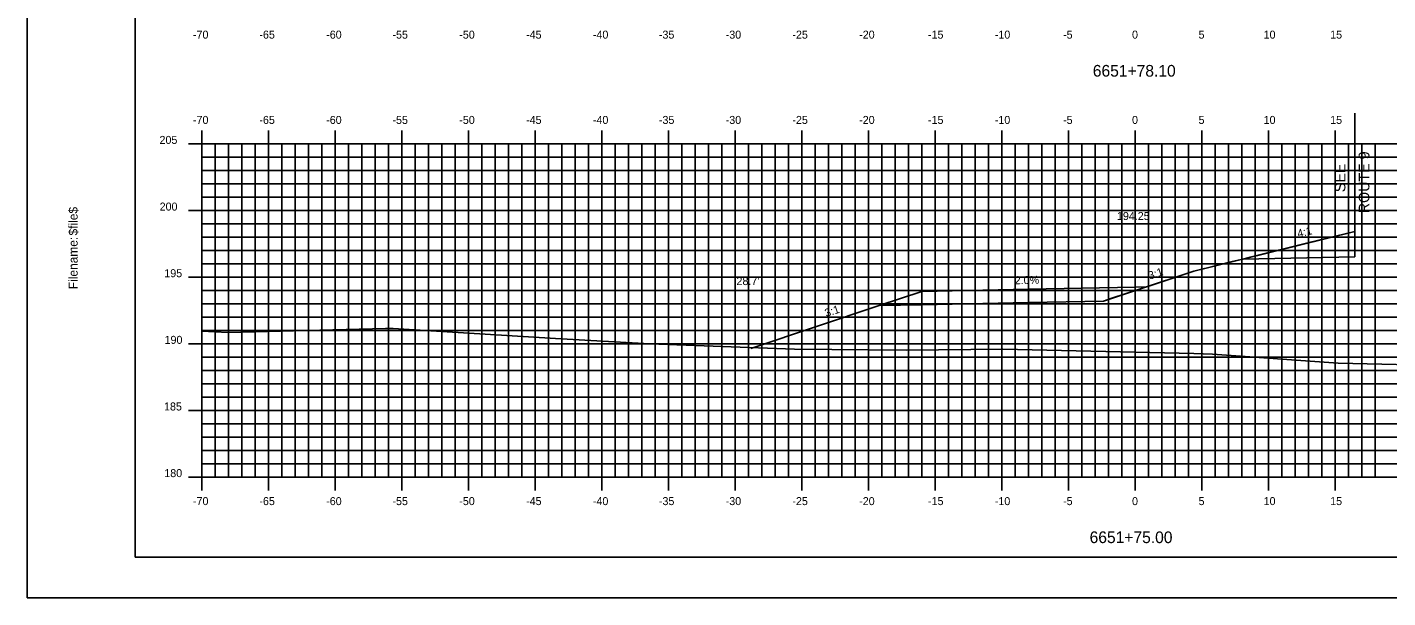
# Model space of a CAD drawing. Extents: x 1723764 to 1723936, y 458501 to 458611.
# Drawn here: x 1723764.4 to 1723866.5, y 458501.2 to 458544 of the extents above; entities that cross this region are included whole.
import ezdxf

# ---------------------------------------------------------------- set-up
doc = ezdxf.new("R2010")
doc.units = 0
for name, color, linetype in [('ANNOTATION', 7, 'Continuous'), ('BORDER', 7, 'Continuous'), ('D_Roadway_Centerline', 7, 'Continuous'), ('D_Roadway_Centerline_Text', 7, 'Continuous'), ('D_Roadway_Drive_Gravel', 7, 'Continuous'), ('D_Roadway_Edge_Shoulder', 7, 'Continuous'), ('D_Roadway_SlopeLines', 7, 'Continuous'), ('D_Roadway_SubGrade', 7, 'Continuous'), ('D_Text_Standard', 7, 'Continuous'), ('H_V ANNOTATION', 7, 'Continuous'), ('MAJOR', 7, 'Continuous'), ('MINOR', 7, 'Continuous'), ('PLOT BOUNDARY', 7, 'Continuous'), ('S_Roadway_Centerline', 7, 'Continuous')]:
    doc.layers.add(name, color=color, linetype=linetype)

msp = doc.modelspace()

# ---------------------------------------------------------------- linework, layer by layer
msp.add_lwpolyline([(1723818.71, 458519.91), (1723818.72, 458519.91), (1723818.79, 458519.93), (1723818.8, 458519.94), (1723818.87, 458519.96), (1723828.35, 458523.12), (1723831.54, 458524.18), (1723839.54, 458524.34), (1723847.54, 458524.5), (1723848.36, 458524.52)])
at = {"layer": 'BORDER'}
msp.add_lwpolyline([(1723772.54, 458504.25), (1723932.54, 458504.25), (1723932.54, 458609.25), (1723772.54, 458609.25)], close=True, dxfattribs=at)
at = {"layer": 'D_Roadway_Centerline'}
msp.add_lwpolyline([(1723845.15, 458523.46), (1723845.79, 458523.67), (1723847.86, 458524.35), (1723851.94, 458525.7), (1723852.77, 458525.91), (1723854.82, 458526.42), (1723855.03, 458526.47), (1723855.6, 458526.61), (1723856.08, 458526.73), (1723856.16, 458526.75), (1723860.49, 458527.83), (1723864, 458528.69)], dxfattribs=at)
at = {"layer": 'D_Roadway_Drive_Gravel'}
msp.add_lwpolyline([(1723847.54, 458524.5), (1723839.54, 458524.34), (1723831.54, 458524.18), (1723828.35, 458523.12), (1723831.54, 458523.18), (1723839.54, 458523.34), (1723845.15, 458523.46)], dxfattribs=at)
at = {"layer": 'D_Roadway_Edge_Shoulder'}
msp.add_line((1723864, 458528.69), (1723864, 458528.44), dxfattribs=at)
msp.add_line((1723864, 458528.69), (1723864, 458528.44), dxfattribs=at)
at = {"layer": 'D_Roadway_SlopeLines'}
for points in [[(1723864, 458528.69), (1723851.94, 458525.7), (1723845.15, 458523.46)], [(1723864, 458528.69), (1723851.94, 458525.7), (1723845.15, 458523.46)], [(1723864, 458528.69), (1723851.94, 458525.7), (1723845.15, 458523.46)], [(1723864, 458528.69), (1723851.94, 458525.7), (1723845.15, 458523.46)], [(1723864, 458528.69), (1723851.94, 458525.7), (1723845.15, 458523.46)], [(1723864, 458528.69), (1723851.94, 458525.7), (1723845.15, 458523.46)], [(1723864, 458528.69), (1723851.94, 458525.7)], [(1723864, 458528.69), (1723851.94, 458525.7)], [(1723864, 458528.69), (1723855.6, 458526.61)], [(1723831.54, 458524.18), (1723828.35, 458523.12), (1723818.87, 458519.96)], [(1723847.54, 458524.5), (1723848.36, 458524.52)]]:
    msp.add_lwpolyline(points, dxfattribs=at)
at = {"layer": 'D_Roadway_SubGrade'}
msp.add_line((1723864, 458537.55), (1723864, 458526.77), dxfattribs=at)
for points in [[(1723864, 458526.77), (1723855.6, 458526.61), (1723864, 458528.69), (1723864, 458528.44)], [(1723864, 458528.44), (1723864, 458528.69), (1723855.6, 458526.61), (1723864, 458526.77)], [(1723864, 458526.77), (1723855.6, 458526.61), (1723864, 458528.69), (1723864, 458528.44)], [(1723864, 458526.77), (1723855.6, 458526.61), (1723864, 458528.69), (1723864, 458528.44)]]:
    msp.add_lwpolyline(points, dxfattribs=at)
at = {"layer": 'MAJOR'}
for p, q in [((1723777.54, 458536.26), (1723777.54, 458535.25)), ((1723782.54, 458536.26), (1723782.54, 458535.25)), ((1723787.54, 458536.26), (1723787.54, 458535.25)), ((1723792.54, 458536.26), (1723792.54, 458535.25)), ((1723797.54, 458536.26), (1723797.54, 458535.25)), ((1723802.54, 458536.26), (1723802.54, 458535.25)), ((1723807.54, 458536.26), (1723807.54, 458535.25)), ((1723812.54, 458536.26), (1723812.54, 458535.25)), ((1723817.54, 458536.26), (1723817.54, 458535.25)), ((1723822.54, 458536.26), (1723822.54, 458535.25)), ((1723827.54, 458536.26), (1723827.54, 458535.25)), ((1723832.54, 458536.26), (1723832.54, 458535.25)), ((1723837.54, 458536.26), (1723837.54, 458535.25)), ((1723842.54, 458536.26), (1723842.54, 458535.25)), ((1723847.54, 458536.26), (1723847.54, 458535.25)), ((1723852.54, 458536.26), (1723852.54, 458535.25)), ((1723857.54, 458536.26), (1723857.54, 458535.25)), ((1723862.54, 458536.26), (1723862.54, 458535.25)), ((1723776.54, 458535.25), (1723777.54, 458535.25)), ((1723777.54, 458535.25), (1723917.54, 458535.25)), ((1723777.54, 458510.25), (1723777.54, 458535.25)), ((1723777.54, 458510.25), (1723777.54, 458535.25)), ((1723777.54, 458535.25), (1723917.54, 458535.25)), ((1723782.54, 458510.25), (1723782.54, 458535.25)), ((1723787.54, 458510.25), (1723787.54, 458535.25)), ((1723792.54, 458510.25), (1723792.54, 458535.25)), ((1723797.54, 458510.25), (1723797.54, 458535.25)), ((1723802.54, 458510.25), (1723802.54, 458535.25)), ((1723807.54, 458510.25), (1723807.54, 458535.25)), ((1723812.54, 458510.25), (1723812.54, 458535.25)), ((1723817.54, 458510.25), (1723817.54, 458535.25)), ((1723822.54, 458510.25), (1723822.54, 458535.25)), ((1723827.54, 458510.25), (1723827.54, 458535.25)), ((1723832.54, 458510.25), (1723832.54, 458535.25)), ((1723837.54, 458510.25), (1723837.54, 458535.25)), ((1723842.54, 458510.25), (1723842.54, 458535.25)), ((1723847.54, 458510.25), (1723847.54, 458535.25)), ((1723852.54, 458510.25), (1723852.54, 458535.25)), ((1723857.54, 458510.25), (1723857.54, 458535.25)), ((1723862.54, 458510.25), (1723862.54, 458535.25)), ((1723776.54, 458530.25), (1723777.54, 458530.25)), ((1723777.54, 458530.25), (1723917.54, 458530.25)), ((1723776.54, 458525.25), (1723777.54, 458525.25)), ((1723777.54, 458525.25), (1723917.54, 458525.25)), ((1723776.54, 458520.25), (1723777.54, 458520.25)), ((1723777.54, 458520.25), (1723917.54, 458520.25)), ((1723776.54, 458515.25), (1723777.54, 458515.25)), ((1723777.54, 458515.25), (1723917.54, 458515.25)), ((1723776.54, 458510.25), (1723777.54, 458510.25)), ((1723777.54, 458510.25), (1723917.54, 458510.25)), ((1723777.54, 458510.25), (1723917.54, 458510.25)), ((1723777.54, 458509.25), (1723777.54, 458510.25)), ((1723782.54, 458509.25), (1723782.54, 458510.25)), ((1723787.54, 458509.25), (1723787.54, 458510.25)), ((1723792.54, 458509.25), (1723792.54, 458510.25)), ((1723797.54, 458509.25), (1723797.54, 458510.25)), ((1723802.54, 458509.25), (1723802.54, 458510.25)), ((1723807.54, 458509.25), (1723807.54, 458510.25)), ((1723812.54, 458509.25), (1723812.54, 458510.25)), ((1723817.54, 458509.25), (1723817.54, 458510.25)), ((1723822.54, 458509.25), (1723822.54, 458510.25)), ((1723827.54, 458509.25), (1723827.54, 458510.25)), ((1723832.54, 458509.25), (1723832.54, 458510.25)), ((1723837.54, 458509.25), (1723837.54, 458510.25)), ((1723842.54, 458509.25), (1723842.54, 458510.25)), ((1723847.54, 458509.25), (1723847.54, 458510.25)), ((1723852.54, 458509.25), (1723852.54, 458510.25)), ((1723857.54, 458509.25), (1723857.54, 458510.25)), ((1723862.54, 458509.25), (1723862.54, 458510.25))]:
    msp.add_line(p, q, dxfattribs=at)
at = {"layer": 'MINOR'}
for p, q in [((1723778.54, 458510.25), (1723778.54, 458535.25)), ((1723779.54, 458510.25), (1723779.54, 458535.25)), ((1723780.54, 458510.25), (1723780.54, 458535.25)), ((1723781.54, 458510.25), (1723781.54, 458535.25)), ((1723783.54, 458510.25), (1723783.54, 458535.25)), ((1723784.54, 458510.25), (1723784.54, 458535.25)), ((1723785.54, 458510.25), (1723785.54, 458535.25)), ((1723786.54, 458510.25), (1723786.54, 458535.25)), ((1723788.54, 458510.25), (1723788.54, 458535.25)), ((1723789.54, 458510.25), (1723789.54, 458535.25)), ((1723790.54, 458510.25), (1723790.54, 458535.25)), ((1723791.54, 458510.25), (1723791.54, 458535.25)), ((1723793.54, 458510.25), (1723793.54, 458535.25)), ((1723794.54, 458510.25), (1723794.54, 458535.25)), ((1723795.54, 458510.25), (1723795.54, 458535.25)), ((1723796.54, 458510.25), (1723796.54, 458535.25)), ((1723798.54, 458510.25), (1723798.54, 458535.25)), ((1723799.54, 458510.25), (1723799.54, 458535.25)), ((1723800.54, 458510.25), (1723800.54, 458535.25)), ((1723801.54, 458510.25), (1723801.54, 458535.25)), ((1723803.54, 458510.25), (1723803.54, 458535.25)), ((1723804.54, 458510.25), (1723804.54, 458535.25)), ((1723805.54, 458510.25), (1723805.54, 458535.25)), ((1723806.54, 458510.25), (1723806.54, 458535.25)), ((1723808.54, 458510.25), (1723808.54, 458535.25)), ((1723809.54, 458510.25), (1723809.54, 458535.25)), ((1723810.54, 458510.25), (1723810.54, 458535.25)), ((1723811.54, 458510.25), (1723811.54, 458535.25)), ((1723813.54, 458510.25), (1723813.54, 458535.25)), ((1723814.54, 458510.25), (1723814.54, 458535.25)), ((1723815.54, 458510.25), (1723815.54, 458535.25)), ((1723816.54, 458510.25), (1723816.54, 458535.25)), ((1723818.54, 458510.25), (1723818.54, 458535.25)), ((1723819.54, 458510.25), (1723819.54, 458535.25)), ((1723820.54, 458510.25), (1723820.54, 458535.25)), ((1723821.54, 458510.25), (1723821.54, 458535.25)), ((1723823.54, 458510.25), (1723823.54, 458535.25)), ((1723824.54, 458510.25), (1723824.54, 458535.25)), ((1723825.54, 458510.25), (1723825.54, 458535.25)), ((1723826.54, 458510.25), (1723826.54, 458535.25)), ((1723828.54, 458510.25), (1723828.54, 458535.25)), ((1723829.54, 458510.25), (1723829.54, 458535.25)), ((1723830.54, 458510.25), (1723830.54, 458535.25)), ((1723831.54, 458510.25), (1723831.54, 458535.25)), ((1723833.54, 458510.25), (1723833.54, 458535.25)), ((1723834.54, 458510.25), (1723834.54, 458535.25)), ((1723835.54, 458510.25), (1723835.54, 458535.25)), ((1723836.54, 458510.25), (1723836.54, 458535.25)), ((1723838.54, 458510.25), (1723838.54, 458535.25)), ((1723839.54, 458510.25), (1723839.54, 458535.25)), ((1723840.54, 458510.25), (1723840.54, 458535.25)), ((1723841.54, 458510.25), (1723841.54, 458535.25)), ((1723843.54, 458510.25), (1723843.54, 458535.25)), ((1723844.54, 458510.25), (1723844.54, 458535.25)), ((1723845.54, 458510.25), (1723845.54, 458535.25)), ((1723846.54, 458510.25), (1723846.54, 458535.25)), ((1723848.54, 458510.25), (1723848.54, 458535.25)), ((1723849.54, 458510.25), (1723849.54, 458535.25)), ((1723850.54, 458510.25), (1723850.54, 458535.25)), ((1723851.54, 458510.25), (1723851.54, 458535.25)), ((1723853.54, 458510.25), (1723853.54, 458535.25)), ((1723854.54, 458510.25), (1723854.54, 458535.25)), ((1723855.54, 458510.25), (1723855.54, 458535.25)), ((1723856.54, 458510.25), (1723856.54, 458535.25)), ((1723858.54, 458510.25), (1723858.54, 458535.25)), ((1723859.54, 458510.25), (1723859.54, 458535.25)), ((1723860.54, 458510.25), (1723860.54, 458535.25)), ((1723861.54, 458510.25), (1723861.54, 458535.25)), ((1723863.54, 458510.25), (1723863.54, 458535.25)), ((1723864.54, 458510.25), (1723864.54, 458535.25)), ((1723865.54, 458510.25), (1723865.54, 458535.25)), ((1723777.54, 458534.25), (1723917.54, 458534.25)), ((1723777.54, 458534.25), (1723778.54, 458534.25)), ((1723777.54, 458533.25), (1723917.54, 458533.25)), ((1723777.54, 458533.25), (1723778.54, 458533.25)), ((1723777.54, 458532.25), (1723917.54, 458532.25)), ((1723777.54, 458532.25), (1723778.54, 458532.25)), ((1723777.54, 458531.25), (1723917.54, 458531.25)), ((1723777.54, 458531.25), (1723778.54, 458531.25)), ((1723777.54, 458529.25), (1723917.54, 458529.25)), ((1723777.54, 458529.25), (1723778.54, 458529.25)), ((1723777.54, 458528.25), (1723917.54, 458528.25)), ((1723777.54, 458528.25), (1723778.54, 458528.25)), ((1723777.54, 458527.25), (1723917.54, 458527.25)), ((1723777.54, 458527.25), (1723778.54, 458527.25)), ((1723777.54, 458526.25), (1723917.54, 458526.25)), ((1723777.54, 458526.25), (1723778.54, 458526.25)), ((1723777.54, 458524.25), (1723917.54, 458524.25)), ((1723777.54, 458524.25), (1723778.54, 458524.25)), ((1723777.54, 458523.25), (1723917.54, 458523.25)), ((1723777.54, 458523.25), (1723778.54, 458523.25)), ((1723777.54, 458522.25), (1723917.54, 458522.25)), ((1723777.54, 458522.25), (1723778.54, 458522.25)), ((1723777.54, 458521.25), (1723917.54, 458521.25)), ((1723777.54, 458521.25), (1723778.54, 458521.25)), ((1723777.54, 458519.25), (1723917.54, 458519.25)), ((1723777.54, 458519.25), (1723778.54, 458519.25)), ((1723777.54, 458518.25), (1723917.54, 458518.25)), ((1723777.54, 458518.25), (1723778.54, 458518.25)), ((1723777.54, 458517.25), (1723917.54, 458517.25)), ((1723777.54, 458517.25), (1723778.54, 458517.25)), ((1723777.54, 458516.25), (1723917.54, 458516.25)), ((1723777.54, 458516.25), (1723778.54, 458516.25)), ((1723777.54, 458514.25), (1723917.54, 458514.25)), ((1723777.54, 458514.25), (1723778.54, 458514.25)), ((1723777.54, 458513.25), (1723917.54, 458513.25)), ((1723777.54, 458513.25), (1723778.54, 458513.25)), ((1723777.54, 458512.25), (1723917.54, 458512.25)), ((1723777.54, 458512.25), (1723778.54, 458512.25)), ((1723777.54, 458511.25), (1723917.54, 458511.25)), ((1723777.54, 458511.25), (1723778.54, 458511.25))]:
    msp.add_line(p, q, dxfattribs=at)
at = {"layer": 'PLOT BOUNDARY'}
msp.add_lwpolyline([(1723764.45, 458501.2), (1723934.45, 458501.2), (1723934.45, 458611.2), (1723764.45, 458611.2)], close=True, dxfattribs=at)
at = {"layer": 'S_Roadway_Centerline'}
msp.add_lwpolyline([(1723777.54, 458521.2), (1723779.5, 458521.1), (1723791.31, 458521.41), (1723791.9, 458521.4), (1723792.28, 458521.38), (1723804.06, 458520.64), (1723811.15, 458520.25), (1723821.99, 458519.84), (1723830.4, 458519.78), (1723837.6, 458519.85), (1723851.94, 458519.53), (1723853.34, 458519.47), (1723862.76, 458518.8), (1723871.49, 458518.59), (1723876.01, 458518.49), (1723882.05, 458518.31), (1723890.84, 458518.15), (1723910.24, 458517.26), (1723910.29, 458517.25), (1723910.54, 458517.25), (1723917.54, 458517.05)], dxfattribs=at)

# ---------------------------------------------------------------- texts
at = {"layer": 'ANNOTATION'}
for s, height, rotation, p in [('ROUTE 9', 0.8, 90, (1723865.1, 458530.05)), ('SEE', 0.8, 90, (1723863.3, 458531.63)), ('4:1', 0.6, 13.6162, (1723859.77, 458528.22)), ('2.0%', 0.6, 1.1458, (1723838.51, 458524.72)), ('3:1', 0.6, 18.4349, (1723848.63, 458525.06)), ('3:1', 0.6, 18.4349, (1723824.37, 458522.25))]:
    msp.add_text(s, height=height, rotation=rotation, dxfattribs=at).set_placement(p)
at = {"layer": 'BORDER'}
for s, p in [('$file$', (1723768.23, 458528.38)), ('Filename:', (1723768.23, 458524.35))]:
    msp.add_text(s, height=0.67, rotation=90, dxfattribs=at).set_placement(p)
at = {"layer": 'D_Roadway_Centerline_Text'}
msp.add_text('194.25', height=0.6, dxfattribs=at).set_placement((1723846.17, 458529.54))
at = {"layer": 'D_Text_Standard'}
msp.add_text("28.7'", height=0.6, dxfattribs=at).set_placement((1723817.64, 458524.66))
at = {"layer": 'H_V ANNOTATION'}
for s, height, p in [('-70', 0.6, (1723776.88, 458543.15)), ('-65', 0.6, (1723781.86, 458543.15)), ('-60', 0.6, (1723786.87, 458543.15)), ('-55', 0.6, (1723791.84, 458543.15)), ('-50', 0.6, (1723796.85, 458543.15)), ('-45', 0.6, (1723801.86, 458543.15)), ('-40', 0.6, (1723806.87, 458543.15)), ('-35', 0.6, (1723811.82, 458543.15)), ('-30', 0.6, (1723816.83, 458543.15)), ('-25', 0.6, (1723821.83, 458543.15)), ('-20', 0.6, (1723826.84, 458543.15)), ('-15', 0.6, (1723832, 458543.15)), ('-10', 0.6, (1723837.01, 458543.15)), ('-5', 0.6, (1723842.13, 458543.15)), ('0', 0.6, (1723847.3, 458543.15)), ('5', 0.6, (1723852.29, 458543.15)), ('10', 0.6, (1723857.17, 458543.15)), ('15', 0.6, (1723862.16, 458543.15)), ('6651+78.10', 0.875, (1723844.36, 458540.3)), ('-70', 0.6, (1723776.88, 458536.75)), ('-65', 0.6, (1723781.86, 458536.75)), ('-60', 0.6, (1723786.87, 458536.75)), ('-55', 0.6, (1723791.84, 458536.75)), ('-50', 0.6, (1723796.85, 458536.75)), ('-45', 0.6, (1723801.86, 458536.75)), ('-40', 0.6, (1723806.87, 458536.75)), ('-35', 0.6, (1723811.82, 458536.75)), ('-30', 0.6, (1723816.83, 458536.75)), ('-25', 0.6, (1723821.83, 458536.75)), ('-20', 0.6, (1723826.84, 458536.75)), ('-15', 0.6, (1723832, 458536.75)), ('-10', 0.6, (1723837.01, 458536.75)), ('-5', 0.6, (1723842.13, 458536.75)), ('0', 0.6, (1723847.3, 458536.75)), ('5', 0.6, (1723852.29, 458536.75)), ('10', 0.6, (1723857.17, 458536.75)), ('15', 0.6, (1723862.16, 458536.75)), ('205', 0.6, (1723774.37, 458535.25)), ('200', 0.6, (1723774.38, 458530.25)), ('195', 0.6, (1723774.73, 458525.25)), ('190', 0.6, (1723774.75, 458520.25)), ('185', 0.6, (1723774.71, 458515.25)), ('180', 0.6, (1723774.73, 458510.25)), ('-70', 0.6, (1723776.88, 458508.15)), ('-65', 0.6, (1723781.86, 458508.15)), ('-60', 0.6, (1723786.87, 458508.15)), ('-55', 0.6, (1723791.84, 458508.15)), ('-50', 0.6, (1723796.85, 458508.15)), ('-45', 0.6, (1723801.86, 458508.15)), ('-40', 0.6, (1723806.87, 458508.15)), ('-35', 0.6, (1723811.82, 458508.15)), ('-30', 0.6, (1723816.83, 458508.15)), ('-25', 0.6, (1723821.83, 458508.15)), ('-20', 0.6, (1723826.84, 458508.15)), ('-15', 0.6, (1723832, 458508.15)), ('-10', 0.6, (1723837.01, 458508.15)), ('-5', 0.6, (1723842.13, 458508.15)), ('0', 0.6, (1723847.3, 458508.15)), ('5', 0.6, (1723852.29, 458508.15)), ('10', 0.6, (1723857.17, 458508.15)), ('15', 0.6, (1723862.16, 458508.15)), ('6651+75.00', 0.875, (1723844.12, 458505.3))]:
    msp.add_text(s, height=height, dxfattribs=at).set_placement(p)
at = {"layer": 'MAJOR'}
msp.add_text('-', height=0.006, dxfattribs=at).set_placement((1723777.54, 458510.25))

doc.saveas('drawing.dxf')
